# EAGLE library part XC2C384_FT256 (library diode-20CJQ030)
XILINX's XC2C384 CoolRunner-II CPLD Description The CoolRunner-II 384-macrocell device is designed for both high performance and low power applications. This lends power savings to high-end communication equipment and high speed to battery operated devices. Due to the low power stand-by and dynamic operation, overall system reliability is improved This device consists of twenty four Function Blocks inter-connected by a low power Advanced Interconnect Matrix (AIM). The AIM feeds 40 true and complement inputs to each Function Block. The Function Blocks consist of a 40 by 56 P-term PLA and 16 macrocells which contain numerous configuration bits that allow for combinational or registered modes of operation. Additionally, these registers can be globally reset or preset and configured as a D or T flip-flop or as a D latch. There are also multiple clock signals, both global and local product term types, configured on a per macrocell basis. Output pin configurations include slew rate limit, bus hold, pull-up, open drain and programmable grounds. A Schmitt-trigger input is available on a per input pin basis. In addition to storing macrocell output states, the macrocell registers may be configured as direct input registers to store signals directly from input pins. Clocking is available on a global or Function Block basis. Three global clocks are available for all Function Blocks as a synchronous clock source. Macrocell registers can be individually configured to power up to the zero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
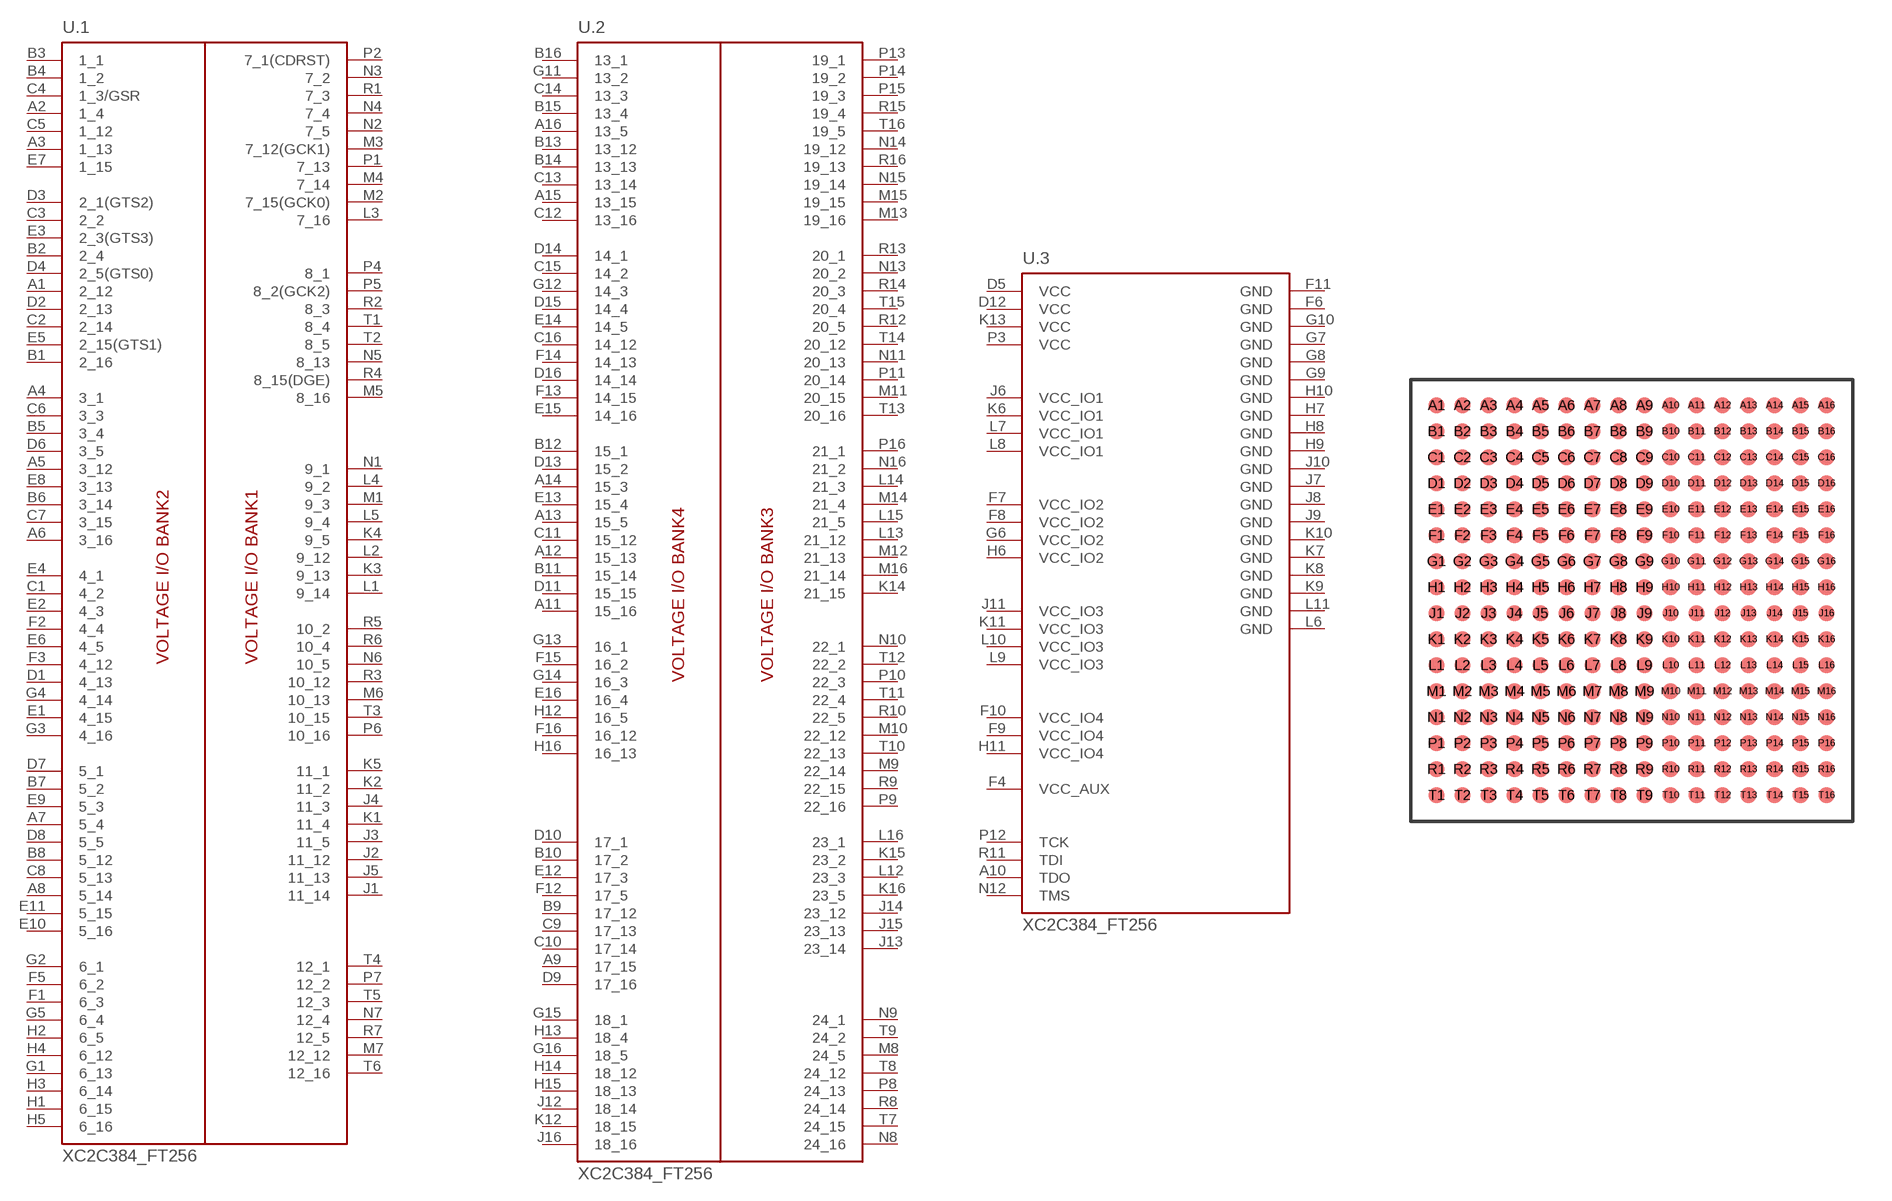
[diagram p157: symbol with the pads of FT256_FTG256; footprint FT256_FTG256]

Designator prefix U; gates .1=XC2C384_FT256_1_12 .2=XC2C384_FT256_13_24 .3=XC2C384_FT256_PWR

## XC2C384_FT256  [FT256_FTG256]
A1  .1:2_12
A2  .1:1_4
A3  .1:1_13
A4  .1:3_1
A5  .1:3_12
A6  .1:3_16
A7  .1:5_4
A8  .1:5_14
A9  .2:17_15
A10  .3:TDO  out
A11  .2:15_16
A12  .2:15_13
A13  .2:15_5
A14  .2:15_3
A15  .2:13_15
A16  .2:13_5
B1  .1:2_16
B2  .1:2_4
B3  .1:1_1
B4  .1:1_2
B5  .1:3_4
B6  .1:3_14
B7  .1:5_2
B8  .1:5_12
B9  .2:17_12
B10  .2:17_2
B11  .2:15_14
B12  .2:15_1
B13  .2:13_12
B14  .2:13_13
B15  .2:13_4
B16  .2:13_1
C1  .1:4_2
C2  .1:2_14
C3  .1:2_2
C4  .1:1_3/GSR
C5  .1:1_12
C6  .1:3_3
C7  .1:3_15
C8  .1:5_13
C9  .2:17_13
C10  .2:17_14
C11  .2:15_12
C12  .2:13_16
C13  .2:13_14
C14  .2:13_3
C15  .2:14_2
C16  .2:14_12
D1  .1:4_13
D2  .1:2_13
D3  .1:2_1(GTS2)
D4  .1:2_5(GTS0)
D5  .3:VCC  pwr
D6  .1:3_5
D7  .1:5_1
D8  .1:5_5
D9  .2:17_16
D10  .2:17_1
D11  .2:15_15
D12  .3:VCC  pwr
D13  .2:15_2
D14  .2:14_1
D15  .2:14_4
D16  .2:14_14
E1  .1:4_15
E2  .1:4_3
E3  .1:2_3(GTS3)
E4  .1:4_1
E5  .1:2_15(GTS1)
E6  .1:4_5
E7  .1:1_15
E8  .1:3_13
E9  .1:5_3
E10  .1:5_16
E11  .1:5_15
E12  .2:17_3
E13  .2:15_4
E14  .2:14_5
E15  .2:14_16
E16  .2:16_4
F1  .1:6_3
F2  .1:4_4
F3  .1:4_12
F4  .3:VCC_AUX  pwr
F5  .1:6_2
F6  .3:GND  pwr
F7  .3:VCC_IO2  pwr
F8  .3:VCC_IO2  pwr
F9  .3:VCC_IO4  pwr
F10  .3:VCC_IO4  pwr
F11  .3:GND  pwr
F12  .2:17_5
F13  .2:14_15
F14  .2:14_13
F15  .2:16_2
F16  .2:16_12
G1  .1:6_13
G2  .1:6_1
G3  .1:4_16
G4  .1:4_14
G5  .1:6_4
G6  .3:VCC_IO2  pwr
G7  .3:GND  pwr
G8  .3:GND  pwr
G9  .3:GND  pwr
G10  .3:GND  pwr
G11  .2:13_2
G12  .2:14_3
G13  .2:16_1
G14  .2:16_3
G15  .2:18_1
G16  .2:18_5
H1  .1:6_15
H2  .1:6_5
H3  .1:6_14
H4  .1:6_12
H5  .1:6_16
H6  .3:VCC_IO2  pwr
H7  .3:GND  pwr
H8  .3:GND  pwr
H9  .3:GND  pwr
H10  .3:GND  pwr
H11  .3:VCC_IO4  pwr
H12  .2:16_5
H13  .2:18_4
H14  .2:18_12
H15  .2:18_13
H16  .2:16_13
J1  .1:11_14
J2  .1:11_12
J3  .1:11_5
J4  .1:11_3
J5  .1:11_13
J6  .3:VCC_IO1  pwr
J7  .3:GND  pwr
J8  .3:GND  pwr
J9  .3:GND  pwr
J10  .3:GND  pwr
J11  .3:VCC_IO3  pwr
J12  .2:18_14
J13  .2:23_14
J14  .2:23_12
J15  .2:23_13
J16  .2:18_16
K1  .1:11_4
K2  .1:11_2
K3  .1:9_13
K4  .1:9_5
K5  .1:11_1
K6  .3:VCC_IO1  pwr
K7  .3:GND  pwr
K8  .3:GND  pwr
K9  .3:GND  pwr
K10  .3:GND  pwr
K11  .3:VCC_IO3  pwr
K12  .2:18_15
K13  .3:VCC  pwr
K14  .2:21_15
K15  .2:23_2
K16  .2:23_5
L1  .1:9_14
L2  .1:9_12
L3  .1:7_16
L4  .1:9_2
L5  .1:9_4
L6  .3:GND  pwr
L7  .3:VCC_IO1  pwr
L8  .3:VCC_IO1  pwr
L9  .3:VCC_IO3  pwr
L10  .3:VCC_IO3  pwr
L11  .3:GND  pwr
L12  .2:23_3
L13  .2:21_12
L14  .2:21_3
L15  .2:21_5
L16  .2:23_1
M1  .1:9_3
M2  .1:7_15(GCK0)
M3  .1:7_12(GCK1)
M4  .1:7_14
M5  .1:8_16
M6  .1:10_13
M7  .1:12_12
M8  .2:24_5
M9  .2:22_14
M10  .2:22_12
M11  .2:20_15
M12  .2:21_13
M13  .2:19_16
M14  .2:21_4
M15  .2:19_15
M16  .2:21_14
N1  .1:9_1
N2  .1:7_5
N3  .1:7_2
N4  .1:7_4
N5  .1:8_13
N6  .1:10_5
N7  .1:12_4
N8  .2:24_16
N9  .2:24_1
N10  .2:22_1
N11  .2:20_13
N12  .3:TMS
N13  .2:20_2
N14  .2:19_12
N15  .2:19_14
N16  .2:21_2
P1  .1:7_13
P2  .1:7_1(CDRST)
P3  .3:VCC  pwr
P4  .1:8_1
P5  .1:8_2(GCK2)
P6  .1:10_16
P7  .1:12_2
P8  .2:24_13
P9  .2:22_16
P10  .2:22_3
P11  .2:20_14
P12  .3:TCK  in
P13  .2:19_1
P14  .2:19_2
P15  .2:19_3
P16  .2:21_1
R1  .1:7_3
R2  .1:8_3
R3  .1:10_12
R4  .1:8_15(DGE)
R5  .1:10_2
R6  .1:10_4
R7  .1:12_5
R8  .2:24_14
R9  .2:22_15
R10  .2:22_5
R11  .3:TDI  in
R12  .2:20_5
R13  .2:20_1
R14  .2:20_3
R15  .2:19_4
R16  .2:19_13
T1  .1:8_4
T2  .1:8_5
T3  .1:10_15
T4  .1:12_1
T5  .1:12_3
T6  .1:12_16
T7  .2:24_15
T8  .2:24_12
T9  .2:24_2
T10  .2:22_13
T11  .2:22_4
T12  .2:22_2
T13  .2:20_16
T14  .2:20_12
T15  .2:20_4
T16  .2:19_5

## Footprint FT256_FTG256 (pad centres in mm)
XILINX 256-BALL FINE-PITCH THIN BGA, 1.00MM PITCH (FT256/FTG256)
smd 0.6 x 0.6: A1 -7.5,7.5; A2 -6.5,7.5; A3 -5.5,7.5; A4 -4.5,7.5; A5 -3.5,7.5; A6 -2.5,7.5; A7 -1.5,7.5; A8 -0.5,7.5; A9 0.5,7.5; A10 1.5,7.5; A11 2.5,7.5; A12 3.5,7.5; A13 4.5,7.5; A14 5.5,7.5; A15 6.5,7.5; A16 7.5,7.5; B1 -7.5,6.5; B2 -6.5,6.5; B3 -5.5,6.5; B4 -4.5,6.5; B5 -3.5,6.5; B6 -2.5,6.5; B7 -1.5,6.5; B8 -0.5,6.5; B9 0.5,6.5; B10 1.5,6.5; B11 2.5,6.5; B12 3.5,6.5; B13 4.5,6.5; B14 5.5,6.5; B15 6.5,6.5; B16 7.5,6.5; C1 -7.5,5.5; C2 -6.5,5.5; C3 -5.5,5.5; C4 -4.5,5.5; C5 -3.5,5.5; C6 -2.5,5.5; C7 -1.5,5.5; C8 -0.5,5.5; C9 0.5,5.5; C10 1.5,5.5; C11 2.5,5.5; C12 3.5,5.5; C13 4.5,5.5; C14 5.5,5.5; C15 6.5,5.5; C16 7.5,5.5; D1 -7.5,4.5; D2 -6.5,4.5; D3 -5.5,4.5; D4 -4.5,4.5; D5 -3.5,4.5; D6 -2.5,4.5; D7 -1.5,4.5; D8 -0.5,4.5; D9 0.5,4.5; D10 1.5,4.5; D11 2.5,4.5; D12 3.5,4.5; D13 4.5,4.5; D14 5.5,4.5; D15 6.5,4.5; D16 7.5,4.5; E1 -7.5,3.5; E2 -6.5,3.5; E3 -5.5,3.5; E4 -4.5,3.5; E5 -3.5,3.5; E6 -2.5,3.5; E7 -1.5,3.5; E8 -0.5,3.5; E9 0.5,3.5; E10 1.5,3.5; E11 2.5,3.5; E12 3.5,3.5; E13 4.5,3.5; E14 5.5,3.5; E15 6.5,3.5; E16 7.5,3.5; F1 -7.5,2.5; F2 -6.5,2.5; F3 -5.5,2.5; F4 -4.5,2.5; F5 -3.5,2.5; F6 -2.5,2.5; F7 -1.5,2.5; F8 -0.5,2.5; F9 0.5,2.5; F10 1.5,2.5; F11 2.5,2.5; F12 3.5,2.5; F13 4.5,2.5; F14 5.5,2.5; F15 6.5,2.5; F16 7.5,2.5; G1 -7.5,1.5; G2 -6.5,1.5; G3 -5.5,1.5; G4 -4.5,1.5; G5 -3.5,1.5; G6 -2.5,1.5; G7 -1.5,1.5; G8 -0.5,1.5; G9 0.5,1.5; G10 1.5,1.5; G11 2.5,1.5; G12 3.5,1.5; G13 4.5,1.5; G14 5.5,1.5; G15 6.5,1.5; G16 7.5,1.5; H1 -7.5,0.5; H2 -6.5,0.5; H3 -5.5,0.5; H4 -4.5,0.5; H5 -3.5,0.5; H6 -2.5,0.5; H7 -1.5,0.5; H8 -0.5,0.5; H9 0.5,0.5; H10 1.5,0.5; H11 2.5,0.5; H12 3.5,0.5; H13 4.5,0.5; H14 5.5,0.5; H15 6.5,0.5; H16 7.5,0.5; J1 -7.5,-0.5; J2 -6.5,-0.5; J3 -5.5,-0.5; J4 -4.5,-0.5; J5 -3.5,-0.5; J6 -2.5,-0.5; J7 -1.5,-0.5; J8 -0.5,-0.5; J9 0.5,-0.5; J10 1.5,-0.5; J11 2.5,-0.5; J12 3.5,-0.5; J13 4.5,-0.5; J14 5.5,-0.5; J15 6.5,-0.5; J16 7.5,-0.5; K1 -7.5,-1.5; K2 -6.5,-1.5; K3 -5.5,-1.5; K4 -4.5,-1.5; K5 -3.5,-1.5; K6 -2.5,-1.5; K7 -1.5,-1.5; K8 -0.5,-1.5; K9 0.5,-1.5; K10 1.5,-1.5; K11 2.5,-1.5; K12 3.5,-1.5; K13 4.5,-1.5; K14 5.5,-1.5; K15 6.5,-1.5; K16 7.5,-1.5; L1 -7.5,-2.5; L2 -6.5,-2.5; L3 -5.5,-2.5; L4 -4.5,-2.5; L5 -3.5,-2.5; L6 -2.5,-2.5; L7 -1.5,-2.5; L8 -0.5,-2.5; L9 0.5,-2.5; L10 1.5,-2.5; L11 2.5,-2.5; L12 3.5,-2.5; L13 4.5,-2.5; L14 5.5,-2.5; L15 6.5,-2.5; L16 7.5,-2.5; M1 -7.5,-3.5; M2 -6.5,-3.5; M3 -5.5,-3.5; M4 -4.5,-3.5; M5 -3.5,-3.5; M6 -2.5,-3.5; M7 -1.5,-3.5; M8 -0.5,-3.5; M9 0.5,-3.5; M10 1.5,-3.5; M11 2.5,-3.5; M12 3.5,-3.5; M13 4.5,-3.5; M14 5.5,-3.5; M15 6.5,-3.5; M16 7.5,-3.5; N1 -7.5,-4.5; N2 -6.5,-4.5; N3 -5.5,-4.5; N4 -4.5,-4.5; N5 -3.5,-4.5; N6 -2.5,-4.5; N7 -1.5,-4.5; N8 -0.5,-4.5; N9 0.5,-4.5; N10 1.5,-4.5; N11 2.5,-4.5; N12 3.5,-4.5; N13 4.5,-4.5; N14 5.5,-4.5; N15 6.5,-4.5; N16 7.5,-4.5; P1 -7.5,-5.5; P2 -6.5,-5.5; P3 -5.5,-5.5; P4 -4.5,-5.5; P5 -3.5,-5.5; P6 -2.5,-5.5; P7 -1.5,-5.5; P8 -0.5,-5.5; P9 0.5,-5.5; P10 1.5,-5.5; P11 2.5,-5.5; P12 3.5,-5.5; P13 4.5,-5.5; P14 5.5,-5.5; P15 6.5,-5.5; P16 7.5,-5.5; R1 -7.5,-6.5; R2 -6.5,-6.5; R3 -5.5,-6.5; R4 -4.5,-6.5; R5 -3.5,-6.5; R6 -2.5,-6.5; R7 -1.5,-6.5; R8 -0.5,-6.5; R9 0.5,-6.5; R10 1.5,-6.5; R11 2.5,-6.5; R12 3.5,-6.5; R13 4.5,-6.5; R14 5.5,-6.5; R15 6.5,-6.5; R16 7.5,-6.5; T1 -7.5,-7.5; T2 -6.5,-7.5; T3 -5.5,-7.5; T4 -4.5,-7.5; T5 -3.5,-7.5; T6 -2.5,-7.5; T7 -1.5,-7.5; T8 -0.5,-7.5; T9 0.5,-7.5; T10 1.5,-7.5; T11 2.5,-7.5; T12 3.5,-7.5; T13 4.5,-7.5; T14 5.5,-7.5; T15 6.5,-7.5; T16 7.5,-7.5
